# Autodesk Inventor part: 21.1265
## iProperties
Created: 2006-02
Part Number: 21.1265
Material: Steel, Mild
Description: M6X22 SHCS LOW HEAD ZINC PLATED
Document SubType Name: Modeling
Standard: DIN 7984
Designer: Andy Moles
Standards Organization: DIN
Language: en-US
Size Designation: M6 x 20
Categories: <MemberInstance><Categories><Category DisplayName="Fasteners" InternalName="e4da775c-781d-43d5-af7c-5136215cf5a6" Mnemonic="FSTN"><Category DisplayName="Bolts"
Density: 1 g/cm^3
Author: Andy Moles
Title: 21.1265 M6X22 SHCS LOW HEAD ZINC PLATED
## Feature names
1. Body [Revolution]
2. Slot [Extrusion]
3. Fillet1
4. Chamfer1
